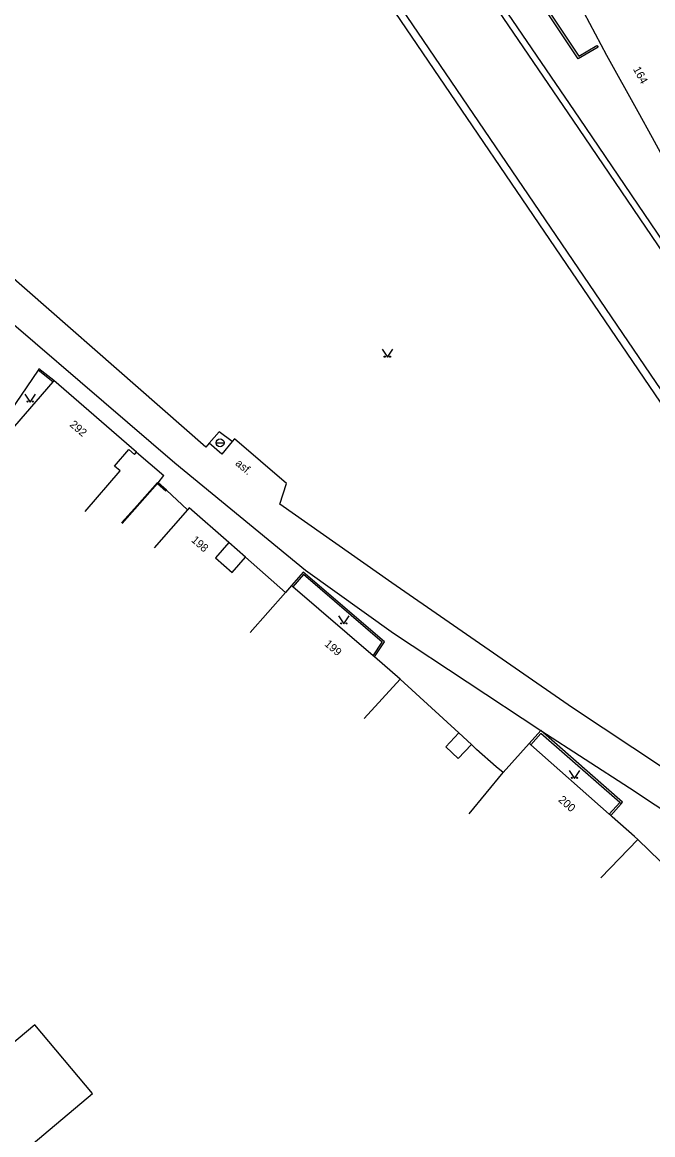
# Model space of a CAD drawing. Extents: x -577457 to -568404, y -1208466 to -1201387.
# Drawn here: x -573659.4 to -573600.3, y -1206669.6 to -1206565.4 of the extents above; entities that cross this region are included whole.
import ezdxf

# ---------------------------------------------------------------- set-up
doc = ezdxf.new("R2010")
doc.units = 0
for name, color, linetype in [('BUDOVY_MĚŘ', 7, 'Continuous'), ('BUDOVY_NEMĚŘ', 7, 'Continuous'), ('POMOC_POPIS', 7, 'Continuous'), ('ROZHRANÍ_PLOCH', 7, 'Continuous'), ('ZN_DOPLŇKOVÉ', 7, 'Continuous'), ('ZN_KULTUR', 7, 'Continuous'), ('Č_POPIS_ORIENT', 7, 'Continuous')]:
    doc.layers.add(name, color=color, linetype=linetype)

msp = doc.modelspace()

# ---------------------------------------------------------------- linework, layer by layer
at = {"layer": 'BUDOVY_MĚŘ'}
for points in [[(-573597.91, -1206578.51), (-573598.81, -1206579), (-573600.35, -1206576.18), (-573601.7, -1206573.77), (-573604.61, -1206568.46), (-573607.82, -1206562.44)], [(-573656.56, -1206599.06), (-573660.74, -1206603.89)], [(-573656.47, -1206598.95), (-573656.56, -1206599.06)], [(-573648.72, -1206605.64), (-573656.47, -1206598.95)], [(-573653.52, -1206611.21), (-573650.26, -1206607.42), (-573650.79, -1206606.96), (-573649.45, -1206605.41), (-573648.92, -1206605.87), (-573648.72, -1206605.64)], [(-573643.94, -1206611.06), (-573647.07, -1206614.62)], [(-573640.05, -1206614.13), (-573643.77, -1206610.86), (-573643.94, -1206611.06)], [(-573640.05, -1206614.13), (-573641.3, -1206615.56), (-573639.76, -1206616.92), (-573638.5, -1206615.5)], [(-573638.5, -1206615.5), (-573640.05, -1206614.13)], [(-573634.75, -1206618.82), (-573638.5, -1206615.5)], [(-573638.07, -1206622.56), (-573634.75, -1206618.82)], [(-573634.19, -1206618.16), (-573634.75, -1206618.82)], [(-573634.06, -1206618.27), (-573634.19, -1206618.16)], [(-573626.54, -1206624.73), (-573634.06, -1206618.27)], [(-573626.41, -1206624.84), (-573626.54, -1206624.73)], [(-573624.01, -1206626.93), (-573626.41, -1206624.84)], [(-573627.39, -1206630.62), (-573624.01, -1206626.93)], [(-573618.51, -1206631.97), (-573624.01, -1206626.93)], [(-573617.3, -1206633.07), (-573618.55, -1206634.36), (-573619.72, -1206633.29), (-573618.51, -1206631.97)], [(-573617.3, -1206633.07), (-573618.51, -1206631.97)], [(-573614.35, -1206635.69), (-573615.01, -1206635.15), (-573616.83, -1206633.52), (-573617.3, -1206633.07)], [(-573611.91, -1206632.95), (-573614.35, -1206635.69)], [(-573611.76, -1206633.08), (-573611.91, -1206632.95)], [(-573604.4, -1206639.59), (-573611.76, -1206633.08)], [(-573617.54, -1206639.54), (-573614.35, -1206635.69)], [(-573604.25, -1206639.72), (-573604.4, -1206639.59)], [(-573601.71, -1206641.97), (-573602.02, -1206641.67), (-573604.12, -1206639.84), (-573604.25, -1206639.72)], [(-573605.19, -1206645.56), (-573601.71, -1206641.97)], [(-573601.71, -1206641.97), (-573592.34, -1206651.06)]]:
    msp.add_lwpolyline(points, dxfattribs=at)
at = {"layer": 'BUDOVY_NEMĚŘ'}
msp.add_lwpolyline([(-573665.12, -1206680.27), (-573659.88, -1206676.27), (-573662.01, -1206673.45), (-573652.83, -1206665.78), (-573658.24, -1206659.32), (-573672.56, -1206671.32)], dxfattribs=at)
at = {"layer": 'ROZHRANÍ_PLOCH'}
for points in [[(-573689.57, -1206452.64), (-573690.07, -1206452.98), (-573686.05, -1206458.82), (-573678.42, -1206470.21), (-573666.08, -1206488.65), (-573649.6, -1206512.89), (-573637.61, -1206530.57), (-573626.02, -1206547.78), (-573607.8, -1206574.53), (-573593.06, -1206596.26), (-573581.29, -1206613.38), (-573552.82, -1206655.05), (-573543.79, -1206667.9), (-573543.3, -1206667.56)], [(-573543.53, -1206667.24), (-573552.3, -1206654.75), (-573580.75, -1206613.1), (-573592.56, -1206595.92), (-573607.2, -1206574.35), (-573625.47, -1206547.53), (-573637.07, -1206530.3), (-573649.43, -1206512.07), (-573665.63, -1206488.25), (-573677.93, -1206469.88), (-573685.57, -1206458.44), (-573689.57, -1206452.64)], [(-573644.52, -1206533.95), (-573644.36, -1206533.84), (-573630.63, -1206554.12), (-573599.03, -1206600.58), (-573587.57, -1206617.39), (-573569.71, -1206643.46), (-573566.78, -1206647.91), (-573567.37, -1206648.31)], [(-573631.22, -1206554.52), (-573599.62, -1206600.98)], [(-573605.45, -1206567.7), (-573607.31, -1206568.78), (-573610.32, -1206564.28), (-573609.57, -1206563.77), (-573609.46, -1206563.93), (-573610.06, -1206564.33), (-573607.25, -1206568.53), (-573605.55, -1206567.54), (-573605.45, -1206567.7)], [(-573641.9, -1206604.82), (-573642.22, -1206605.19), (-573665.34, -1206584.95), (-573668.18, -1206582.41), (-573679.91, -1206572.36), (-573682.86, -1206569.45), (-573685.81, -1206566.55), (-573686.01, -1206566.35), (-573686.37, -1206565.94), (-573686.66, -1206565.56), (-573686.91, -1206565.21)], [(-573670.24, -1206585.01), (-573667.12, -1206587.78), (-573645.13, -1206606.66), (-573632.87, -1206616.72), (-573624.61, -1206622.63), (-573610.82, -1206631.75)], [(-573657.94, -1206597.96), (-573661.62, -1206603.33)], [(-573656.47, -1206598.95), (-573657.86, -1206597.84), (-573657.94, -1206597.96)], [(-573656.56, -1206599.06), (-573657.94, -1206597.96)], [(-573639.75, -1206604.66), (-573640.97, -1206603.76), (-573641.9, -1206604.82)], [(-573585.11, -1206644.69), (-573607.83, -1206629.61), (-573624.78, -1206617.91), (-573635.27, -1206610.53), (-573634.66, -1206608.6), (-573639.52, -1206604.4), (-573639.75, -1206604.66)], [(-573639.75, -1206604.66), (-573640.73, -1206605.85), (-573641.9, -1206604.82)], [(-573650.11, -1206612.29), (-573648.92, -1206610.94), (-573648.65, -1206610.64), (-573646.75, -1206608.49)], [(-573646.75, -1206608.59), (-573645.97, -1206609.28), (-573645.92, -1206609.23)], [(-573646.7, -1206608.54), (-573646.17, -1206607.83)], [(-573645.92, -1206609.23), (-573646.7, -1206608.54)], [(-573626.41, -1206624.84), (-573625.48, -1206623.43), (-573633.08, -1206616.89), (-573634.19, -1206618.16)], [(-573626.54, -1206624.73), (-573625.7, -1206623.46), (-573633.06, -1206617.13), (-573634.06, -1206618.27)], [(-573610.82, -1206631.75), (-573611.91, -1206632.95)], [(-573610.8, -1206632.03), (-573611.76, -1206633.08)], [(-573610.82, -1206631.75), (-573602.5, -1206637.13), (-573588.15, -1206646.62)], [(-573603.27, -1206638.62), (-573603.14, -1206638.47), (-573610.82, -1206631.75)], [(-573604.4, -1206639.59), (-573603.42, -1206638.49)], [(-573604.25, -1206639.72), (-573603.27, -1206638.62)]]:
    msp.add_lwpolyline(points, dxfattribs=at)
at = {"layer": 'ZN_DOPLŇKOVÉ'}
msp.add_line((-573641.26, -1206604.78), (-573640.51, -1206604.78), dxfattribs=at)
for points in [[(-573648.72, -1206605.64), (-573646.17, -1206607.83)], [(-573650.06, -1206612.33), (-573646.75, -1206608.59)], [(-573646.75, -1206608.59), (-573646.7, -1206608.54)], [(-573643.94, -1206611.06), (-573645.92, -1206609.23)], [(-573603.42, -1206638.49), (-573610.8, -1206632.03)], [(-573603.27, -1206638.62), (-573603.42, -1206638.49)]]:
    msp.add_lwpolyline(points, dxfattribs=at)
msp.add_circle((-573640.88, -1206604.78), 0.375, dxfattribs=at)
at = {"layer": 'ZN_KULTUR'}
for points in [[(-573625.7, -1206596), (-573625.2, -1206596.75), (-573624.7, -1206596)], [(-573659.19, -1206600.21), (-573658.69, -1206600.96), (-573658.19, -1206600.21)], [(-573629.77, -1206621.01), (-573629.27, -1206621.76), (-573628.77, -1206621.01)], [(-573608.15, -1206635.48), (-573607.65, -1206636.23), (-573607.15, -1206635.48)]]:
    msp.add_lwpolyline(points, dxfattribs=at)
for centre in [(-573625.45, -1206596.7), (-573624.95, -1206596.7), (-573658.94, -1206600.91), (-573658.44, -1206600.91), (-573629.52, -1206621.71), (-573629.02, -1206621.71), (-573607.9, -1206636.18), (-573607.4, -1206636.18)]:
    msp.add_circle(centre, 0.05, dxfattribs=at)

# ---------------------------------------------------------------- texts
at = {"layer": 'POMOC_POPIS'}
msp.add_text('asf.', height=0.75, rotation=319.55, dxfattribs=at).set_placement((-573639.51, -1206606.8))
at = {"layer": 'Č_POPIS_ORIENT'}
for s, rotation, p in [('164', 298.77, (-573602.19, -1206569.75)), ('292', 319.17, (-573655.04, -1206603.16)), ('198', 318.67, (-573643.64, -1206613.98)), ('199', 319.39, (-573631.15, -1206623.73)), ('200', 318.55, (-573609.23, -1206638.33))]:
    msp.add_text(s, height=0.75, rotation=rotation, dxfattribs=at).set_placement(p)

doc.saveas('drawing.dxf')
